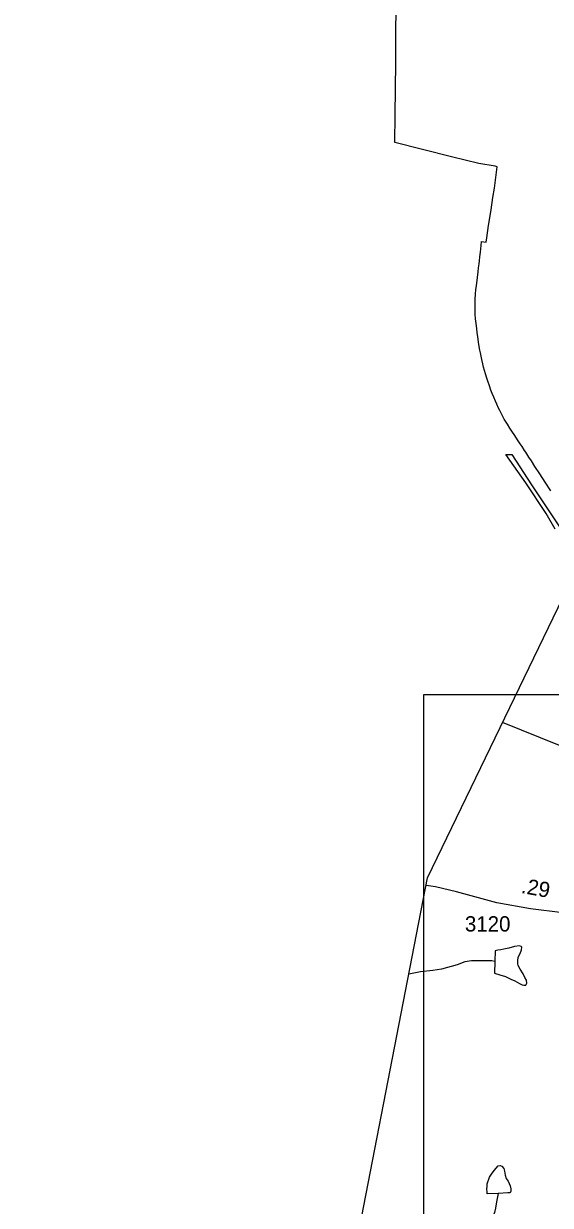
# Model space of a CAD drawing. Extents: x 2001466 to 2224147, y 644118 to 847247.
# Drawn here: x 2017207 to 2021505, y 741433 to 751088 of the extents above; entities that cross this region are included whole.
import ezdxf

# ---------------------------------------------------------------- set-up
doc = ezdxf.new("R2010")
doc.units = 0
for name, color, linetype in [('Exist Boundary Political City Limit New', 7, 'Continuous'), ('Exist Boundary Political CountyLine', 7, 'Continuous'), ('Exist Hydrographic Misc Water Feature', 7, 'Continuous'), ('Exist Road Secondary Mileage Hundredths English Label', 7, 'Continuous'), ('Exist Road Secondary Type 51 Attributed', 7, 'Continuous'), ('Exist Road Secondary Type 51 Number Label', 7, 'Continuous'), ('Map Preparation Boundary City Limit Buffer Line', 7, 'Continuous'), ('Map Preparation Inset Cut Line', 7, 'Continuous')]:
    doc.layers.add(name, color=color, linetype=linetype)

msp = doc.modelspace()

# ---------------------------------------------------------------- linework, layer by layer
at = {"layer": 'Exist Boundary Political City Limit New'}
for points in [[(2020945.6, 748343.4), (2020939.6, 748372.2), (2020934.8, 748398.9), (2020930.9, 748420), (2020925.4, 748450.8), (2020919.8, 748485.4), (2020912.8, 748532.4), (2020909.1, 748561.1), (2020904.6, 748598.1), (2020899.6, 748639.3), (2020895.5, 748676.6), (2020893, 748715.1), (2020892, 748751.7), (2020892, 748793.2), (2020892.9, 748834.4), (2020895.2, 748881), (2020898.6, 748913.7), (2020903.1, 748947.6), (2020908.2, 748989.8), (2020910.9, 749013.2), (2020916.1, 749059.2), (2020919.9, 749091.7), (2020923.9, 749125.8), (2020927, 749151.5), (2020930.5, 749182.3), (2020934.9, 749222.1), (2020940.4, 749274.9), (2020943.8, 749307.3), (2020980.8, 749302.3), (2020985.8, 749338.2), (2021000.9, 749438.2), (2021022.2, 749567.6), (2021037.2, 749666.9), (2021048.4, 749742.7), (2021058.6, 749810.4), (2021071.8, 749919), (2021054.2, 749923.5), (2020920.8, 749944.5), (2020699.2, 750000), (2020236, 750116), (2020239.5, 750340.1), (2020243.4, 750769.9), (2020245.5, 751051.7), (2020252.4, 751425.3)], [(2021509.5, 747271.9), (2021463.8, 747342), (2021419.1, 747410.6), (2021380.1, 747470.5), (2021351.2, 747514.9), (2021330.9, 747546.5), (2021304.2, 747588), (2021295.4, 747601.8), (2021275.2, 747632.3), (2021259.4, 747656), (2021237.5, 747688.7), (2021214.6, 747723.6), (2021191.8, 747758.9), (2021175.4, 747783.6), (2021154.9, 747815.2), (2021139.8, 747840), (2021129.8, 747857.4), (2021115.6, 747883), (2021103.2, 747906.2), (2021092.9, 747926.6), (2021083, 747946.9), (2021068.5, 747977.9), (2021057.1, 748003.4), (2021043, 748036.2), (2021030.8, 748066.1), (2021020, 748094.1), (2021007.8, 748128.7), (2020995.1, 748166.1), (2020987.2, 748190.6), (2020976.5, 748225.9), (2020968.5, 748253.8), (2020960.8, 748282), (2020953.6, 748309.7), (2020945.6, 748343.4)], [(2021545.8, 746958.1), (2021470.1, 747084.7), (2021305, 747337.6), (2021141, 747568.2), (2021161.4, 747568.8), (2021191.1, 747568.9), (2021351, 747321.2), (2021596.4, 746951)]]:
    msp.add_lwpolyline(points, dxfattribs=at)
at = {"layer": 'Exist Boundary Political CountyLine'}
msp.add_lwpolyline([(2006817.6, 695750.4), (2007499.4, 697710.6), (2010412.6, 706844.6), (2011918.3, 711705.5), (2013748.8, 717730), (2014941.8, 722041.3), (2015284.7, 723238.9), (2015749.8, 724659.3), (2016152.8, 726117.8), (2016501.7, 727373.6), (2016860.6, 728619.5), (2017411.9, 730567.4), (2017756.8, 731851.4), (2018083.6, 732956.8), (2018350.2, 733869.6), (2018833.4, 735584.8), (2018918.2, 735898.3), (2019734.3, 740137.7), (2020502.6, 744108.1), (2021805.5, 746807.9), (2022821.6, 749625), (2023527, 751602.5)], dxfattribs=at)
at = {"layer": 'Exist Hydrographic Misc Water Feature'}
for points in [[(2022378.7, 744818.5), (2022013.3, 744972.7), (2021579.4, 745191.5), (2021115.4, 745377.9)], [(2021053.4, 743425.5), (2021050.3, 743331.2), (2021094.4, 743315.5), (2021140.4, 743303.1), (2021182.4, 743281.8), (2021216.6, 743268), (2021252.5, 743245.9), (2021276.3, 743235.5), (2021288.4, 743232), (2021306.4, 743231.6), (2021314.2, 743247.9), (2021310.3, 743273.4), (2021298.2, 743293.3), (2021282.3, 743325.6), (2021258.3, 743361.4), (2021244.1, 743393.7), (2021240, 743407.7), (2021240.2, 743431.5), (2021244.1, 743461.8), (2021258.1, 743489.4), (2021270.2, 743519.5), (2021274, 743541.6), (2021266.1, 743547.5), (2021254, 743553.5), (2021213.8, 743547.7), (2021166, 743535.6), (2021126, 743525.7), (2021100.2, 743519.7), (2021078, 743517.6), (2021056.1, 743511.6), (2021053.4, 743425.5)], [(2021053.4, 743425.5), (2021028.2, 743431.8), (2020998.3, 743431.5), (2020958.3, 743431.5), (2020898, 743431.1), (2020862.3, 743431), (2020808.2, 743423.1), (2020744.4, 743399), (2020618.3, 743363), (2020546.5, 743350.5), (2020444.6, 743340.3), (2020350.2, 743320.5)], [(2021080.9, 741530.9), (2020989.2, 741526.2), (2020989, 741542.6), (2020987.2, 741566.5), (2020989, 741588.5), (2020989, 741609.1), (2021009.1, 741662.8), (2021024.9, 741688.7), (2021046.9, 741718.6), (2021080.9, 741754.8), (2021096.9, 741758.6), (2021109, 741752.6), (2021124.8, 741735.1), (2021130.9, 741711.2), (2021136.9, 741680.7), (2021144.9, 741652.7), (2021161.1, 741631), (2021169.1, 741612.8), (2021177.1, 741592.9), (2021183, 741566.6), (2021183, 741549.3), (2021177.1, 741534.7), (2021159, 741535), (2021080.9, 741530.9)], [(2021080.9, 741530.9), (2021075.4, 741503.1), (2021065.3, 741462.3), (2021057.5, 741410.8), (2021049.3, 741374.8), (2021031.5, 741324.3), (2021017.5, 741254.9), (2021007.7, 741208.4), (2021003.6, 741176.4), (2021005.6, 741146.1), (2021001.7, 741078.1), (2020990.1, 741040.6), (2020975.9, 741006.4), (2020967.9, 740996.7), (2020950.7, 740973.5), (2020946.4, 740967.6)]]:
    msp.add_lwpolyline(points, dxfattribs=at)
at = {"layer": 'Exist Road Secondary Type 51 Attributed'}
msp.add_lwpolyline([(2021996.5, 743778.7), (2021821.1, 743801.2), (2021607.6, 743823.9), (2021344.3, 743856.1), (2021068.8, 743904.3), (2020740.6, 743994.4), (2020568.4, 744034.7), (2020490.7, 744047.1)], dxfattribs=at)
at = {"layer": 'Map Preparation Boundary City Limit Buffer Line'}
for points in [[(2020945.6, 748343.4), (2020939.6, 748372.2), (2020934.8, 748398.9), (2020930.9, 748420), (2020925.4, 748450.8), (2020919.8, 748485.4), (2020912.8, 748532.4), (2020909.1, 748561.1), (2020904.6, 748598.1), (2020899.6, 748639.3), (2020895.5, 748676.6), (2020893, 748715.1), (2020892, 748751.7), (2020892, 748793.2), (2020892.9, 748834.4), (2020895.2, 748881), (2020898.6, 748913.7), (2020903.1, 748947.6), (2020908.2, 748989.8), (2020910.9, 749013.2), (2020916.1, 749059.2), (2020919.9, 749091.7), (2020923.9, 749125.8), (2020927, 749151.5), (2020930.5, 749182.3), (2020934.9, 749222.1), (2020940.4, 749274.9), (2020943.8, 749307.3), (2020980.8, 749302.3), (2020985.8, 749338.2), (2021000.9, 749438.2), (2021022.2, 749567.6), (2021037.2, 749666.9), (2021048.4, 749742.7), (2021058.6, 749810.4), (2021071.8, 749919), (2021054.2, 749923.5), (2020920.8, 749944.5), (2020699.2, 750000), (2020236, 750116), (2020239.5, 750340.1), (2020243.4, 750769.9), (2020245.5, 751051.7), (2020252.4, 751425.3)], [(2021509.5, 747271.9), (2021463.8, 747342), (2021419.1, 747410.6), (2021380.1, 747470.5), (2021351.2, 747514.9), (2021330.9, 747546.5), (2021304.2, 747588), (2021295.4, 747601.8), (2021275.2, 747632.3), (2021259.4, 747656), (2021237.5, 747688.7), (2021214.6, 747723.6), (2021191.8, 747758.9), (2021175.4, 747783.6), (2021154.9, 747815.2), (2021139.8, 747840), (2021129.8, 747857.4), (2021115.6, 747883), (2021103.2, 747906.2), (2021092.9, 747926.6), (2021083, 747946.9), (2021068.5, 747977.9), (2021057.1, 748003.4), (2021043, 748036.2), (2021030.8, 748066.1), (2021020, 748094.1), (2021007.8, 748128.7), (2020995.1, 748166.1), (2020987.2, 748190.6), (2020976.5, 748225.9), (2020968.5, 748253.8), (2020960.8, 748282), (2020953.6, 748309.7), (2020945.6, 748343.4)], [(2021545.8, 746958.1), (2021470.1, 747084.7), (2021305, 747337.6), (2021141, 747568.2), (2021161.4, 747568.8), (2021191.1, 747568.9), (2021351, 747321.2), (2021596.4, 746951)]]:
    msp.add_lwpolyline(points, dxfattribs=at)
at = {"layer": 'Map Preparation Inset Cut Line'}
for p, q in [((2021250.9, 745607.9), (2022323, 745607.9)), ((2020472.9, 740711.9), (2020472.9, 743977.7))]:
    msp.add_line(p, q, dxfattribs=at)
msp.add_lwpolyline([(2020472.9, 743977.7), (2020472.9, 745607.9), (2021250.9, 745607.9)], dxfattribs=at)

# ---------------------------------------------------------------- texts
at = {"layer": 'Exist Road Secondary Mileage Hundredths English Label'}
msp.add_text('.29', height=125, rotation=349.71024, dxfattribs=at).set_placement((2021261.7, 743986.3))
at = {"layer": 'Exist Road Secondary Type 51 Number Label'}
msp.add_text('3120', height=125, dxfattribs=at).set_placement((2020808.1, 743670.3))

doc.saveas('drawing.dxf')
